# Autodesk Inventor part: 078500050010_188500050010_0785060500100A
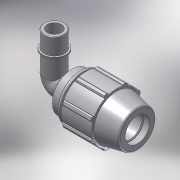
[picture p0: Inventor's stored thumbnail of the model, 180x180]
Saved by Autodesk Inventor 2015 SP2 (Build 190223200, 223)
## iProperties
Created: 2017-02
Part Number: 078500050010_188500050010_0785060500100A
Material: PVC-Piping
Description: PLASSON 90° ELBOW MALE ADAPTOR 50-1"
Document SubType Name: Modeling
Designer: KIM
Mass: 92.6774 g
Surface Area: 199.44 cm^2
Volume: 66.1981 cm^3
Density: 1.4 g/cm^3
Appearance: Smooth - White
Author: KIM
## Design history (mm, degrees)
derived "07850.ipt"
feature "Solid1::07850.ipt"
tag "TaggingFeature1"
body "Solid1"
other parameters: "d4" = 11.66667, "d5" = 35, "d7" = 96, "d11" = 4.66667, "d13" = 120 deg, "d15" = 12 deg, "d16" = 83.52, "d18" = 2.5, "d19" = 35 deg, "d20" = 17.5 deg, "d21" = 89.28, "d23" = 0, "d25" = 360 deg, "d27" = 1.92, "d33" = 1, "d42" = 51.8, "d43" = 2.88, "d46" = 1.5, "d68" = 4.66667, "d72" = 71, "d73" = 33.249, "d75" = 38.23635, "d76" = 23.2743, "d77" = 22, "d79" = 13.2996, "d80" = 0.99747, "d83" = 0, "d84" = 0, "d91" = 72, "d93" = 93, "d94" = 33.249, "d95" = 23.2743, "d96" = 14, "d97" = 50 deg, "E_" = 96, "l_" = 93, "A_1" = 71, "R_" = 33.249
